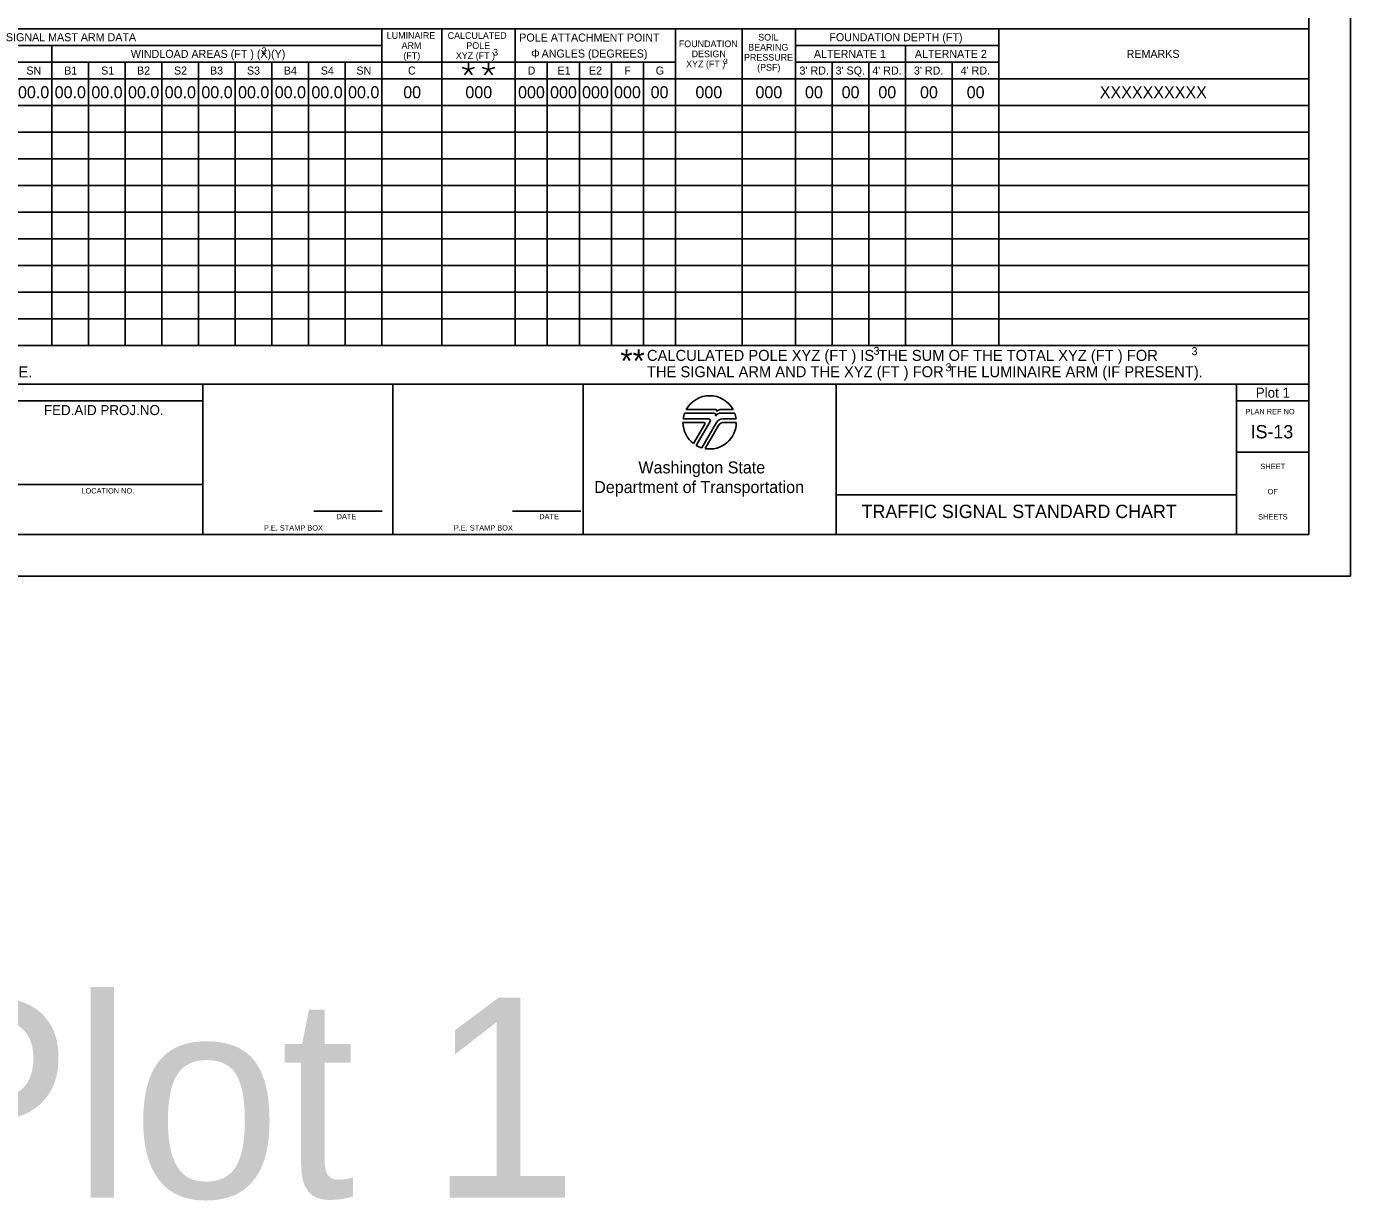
# Model space of a CAD drawing. Extents: x 99999.1 to 100045.6, y 99995 to 100042.
# Drawn here: x 100006.13 to 100016.06, y 99995.01 to 100003.81 of the extents above; entities that cross this region are included whole.
import ezdxf

# ---------------------------------------------------------------- set-up
doc = ezdxf.new("R2010")
doc.units = 0
for name, color, linetype in [('Level 20', 7, 'Continuous'), ('Level 40', 7, 'Continuous'), ('Level 51', 7, 'Continuous'), ('Level 55', 7, 'Continuous'), ('SH_GI_PlotLimits', 7, 'Continuous'), ('SH_GI_SheetBorder', 7, 'Continuous'), ('SH_GI_SheetLocationText', 7, 'Continuous'), ('SH_GI_SheetTextInCells', 7, 'Continuous'), ('SH_GI_TitleBlockText', 7, 'Continuous'), ('SH_GI_WSDOTLogo', 7, 'Continuous'), ('TR_SG_SignalsUserLevel1New', 7, 'Continuous')]:
    doc.layers.add(name, color=color, linetype=linetype)

msp = doc.modelspace()

# ---------------------------------------------------------------- linework, layer by layer
at = {"layer": 'Level 20'}
for p, q in [((100009.401, 100003.4998), (100009.448, 100003.4845)), ((100009.448, 100003.4845), (100009.419, 100003.4445)), ((100009.448, 100003.4845), (100009.448, 100003.534)), ((100009.448, 100003.4845), (100009.495, 100003.4998)), ((100009.448, 100003.4845), (100009.4771, 100003.4445)), ((100009.5518, 100003.4998), (100009.5988, 100003.4845)), ((100009.5988, 100003.4845), (100009.5697, 100003.4445)), ((100009.5988, 100003.4845), (100009.5988, 100003.534)), ((100009.5988, 100003.4845), (100009.6458, 100003.4998)), ((100009.5988, 100003.4845), (100009.6278, 100003.4445))]:
    msp.add_line(p, q, dxfattribs=at)
at = {"layer": 'Level 40'}
for p, q in [((100000, 100003.7903), (100015.7438, 100003.7903)), ((100008.8, 100003.7903), (100008.8, 100001.4153)), ((100009.25, 100003.7903), (100009.25, 100001.4153)), ((100009.8, 100003.7903), (100009.8, 100001.4153)), ((100011, 100003.7903), (100011, 100001.4153)), ((100011.5, 100003.7903), (100011.5, 100001.4153)), ((100011.9, 100003.7903), (100011.9, 100001.4153)), ((100013.425, 100003.7903), (100013.425, 100001.4153)), ((100003.85, 100003.6653), (100008.8, 100003.6653)), ((100006.325, 100003.6653), (100006.325, 100001.4153)), ((100011.9, 100003.6653), (100013.425, 100003.6653)), ((100012.725, 100003.6653), (100012.725, 100001.4153)), ((100003.35, 100003.5403), (100011, 100003.5403)), ((100006.6, 100003.5403), (100006.6, 100001.4153)), ((100006.875, 100003.5403), (100006.875, 100001.4153)), ((100007.15, 100003.5403), (100007.15, 100001.4153)), ((100007.425, 100003.5403), (100007.425, 100001.4153)), ((100007.7, 100003.5403), (100007.7, 100001.4153)), ((100007.975, 100003.5403), (100007.975, 100001.4153)), ((100008.25, 100003.5403), (100008.25, 100001.4153)), ((100008.525, 100003.5403), (100008.525, 100001.4153)), ((100010.04, 100003.5403), (100010.04, 100001.4153)), ((100010.28, 100003.5403), (100010.28, 100001.4153)), ((100010.52, 100003.5403), (100010.52, 100001.4153)), ((100010.76, 100003.5403), (100010.76, 100001.4153)), ((100011.9, 100003.5403), (100013.425, 100003.5403)), ((100012.175, 100003.5403), (100012.175, 100001.4153)), ((100012.45, 100003.5403), (100012.45, 100001.4153)), ((100013.075, 100003.5403), (100013.075, 100001.4153)), ((100000, 100003.4153), (100015.75, 100003.4153)), ((100000, 100003.2153), (100015.75, 100003.2153)), ((100000, 100003.0153), (100015.75, 100003.0153)), ((100000, 100002.8153), (100015.75, 100002.8153)), ((100000, 100002.6153), (100015.75, 100002.6153)), ((100000, 100002.4153), (100015.75, 100002.4153)), ((100000, 100002.2153), (100015.75, 100002.2153)), ((100000, 100002.0153), (100015.75, 100002.0153)), ((100000, 100001.8153), (100015.75, 100001.8153)), ((100000, 100001.6153), (100015.75, 100001.6153)), ((100000, 100001.4153), (100015.7438, 100001.4153))]:
    msp.add_line(p, q, dxfattribs=at)
at = {"layer": 'SH_GI_PlotLimits'}
msp.add_lwpolyline([(99999.0625, 99999.6875), (100016.0625, 99999.6875), (100016.0625, 100010.6875), (99999.0625, 100010.6875)], close=True, dxfattribs=at)
at = {"layer": 'SH_GI_SheetBorder'}
for p, q in [((100015.75, 100010.375), (100015.75, 100000)), ((100000, 100001.1259), (100015.75, 100001.1259)), ((100007.4566, 100000), (100007.4566, 100001.1259)), ((100008.8828, 100000), (100008.8828, 100001.1259)), ((100010.3089, 100001.1259), (100010.3089, 100000)), ((100012.2055, 100001.1259), (100012.2055, 100000)), ((100015.2079, 100001.1259), (100015.2079, 100000)), ((100000, 100001.0008), (100007.4566, 100001.0008)), ((100015.2079, 100001.0008), (100015.75, 100001.0008)), ((100015.2079, 100000.6176), (100015.75, 100000.6176)), ((100007.4566, 100000.3753), (100005.4466, 100000.3753)), ((100012.2055, 100000.2955), (100015.2079, 100000.2955)), ((100008.2903, 100000.1733), (100008.802, 100000.1733)), ((100009.7797, 100000.1733), (100010.2914, 100000.1733)), ((100000, 100000), (100015.75, 100000))]:
    msp.add_line(p, q, dxfattribs=at)
at = {"layer": 'SH_GI_WSDOTLogo'}
for p, q in [((100011.2894, 100000.9094), (100011.0697, 100000.9094)), ((100011.303, 100000.9354), (100011.0815, 100000.9354)), ((100011.433, 100000.9354), (100011.3351, 100000.9354)), ((100011.343, 100000.9094), (100011.3429, 100000.9094)), ((100011.4448, 100000.9094), (100011.343, 100000.9094)), ((100011.0572, 100000.84), (100011.2148, 100000.84)), ((100011.059, 100000.8661), (100011.2496, 100000.8661)), ((100011.222, 100000.8277), (100011.1364, 100000.6807)), ((100011.261, 100000.8464), (100011.1567, 100000.6672)), ((100011.1989, 100000.6487), (100011.3089, 100000.839)), ((100011.2244, 100000.6428), (100011.3242, 100000.8156)), ((100011.3558, 100000.8661), (100011.4555, 100000.8661)), ((100011.3655, 100000.8394), (100011.4572, 100000.8394))]:
    msp.add_line(p, q, dxfattribs=at)
for centre, radius, start, end in [((100011.2572, 100000.84), 0.2, 28.47865, 151.53204), ((100011.2572, 100000.84), 0.2, 159.69598, 172.50569), ((100011.2894, 100000.8946), 0.0148, 327.8418, 89.99855), ((100011.3429, 100000.861), 0.0484, 89.99529, 147.82376), ((100011.303, 100000.9263), 0.00903, 329.87418, 90.00328), ((100011.3352, 100000.9066), 0.0287, 90.00721, 148.16763), ((100011.2572, 100000.84), 0.2, 7.49431, 20.29406), ((100011.2572, 100000.84), 0.2, 179.99864, 232.84327), ((100011.2149, 100000.8318), 0.0082, 329.74356, 90), ((100011.2572, 100000.84), 0.2, 260.54554, 359.80857), ((100011.2497, 100000.853), 0.0131, 329.76834, 90), ((100011.3558, 100000.8119), 0.0542, 90, 149.99738), ((100011.3654, 100000.7918), 0.0476, 90, 150.05432), ((100011.2572, 100000.84), 0.2, 239.79292, 253.0448)]:
    msp.add_arc(centre, radius, start, end, dxfattribs=at)

# ---------------------------------------------------------------- texts
at = {"layer": 'Level 40'}
msp.add_text('2', height=0.05, dxfattribs=at).set_placement((100007.8967, 100003.602))
at = {"layer": 'Level 51'}
for s, height, p in [('SIGNAL MAST ARM DATA', 0.06, (100005.9802, 100003.6978)), ('LUMINAIRE', 0.05, (100008.8359, 100003.7157)), ('CALCULATED', 0.05, (100009.2928, 100003.7155)), ('POLE ATTACHMENT POINT', 0.06, (100009.8296, 100003.6953)), ('FOUNDATION DEPTH (FT)', 0.06, (100012.1549, 100003.6978)), ('ARM', 0.05, (100008.9472, 100003.6403)), ('POLE', 0.05, (100009.4328, 100003.6401)), ('FOUNDATION', 0.05, (100011.026, 100003.6532)), ('BEARING', 0.05, (100011.5463, 100003.6274)), ('SOIL', 0.05, (100011.6212, 100003.7028)), ('WINDLOAD AREAS (FT ) (X)(Y)', 0.06, (100006.9169, 100003.5728)), ('(FT)', 0.05, (100008.9609, 100003.5649)), ('XYZ (FT )', 0.05, (100009.3541, 100003.5647)), ('3', 0.05, (100009.6332, 100003.5903)), ('Φ', 0.06, (100009.9186, 100003.5753)), (' ANGLES (DEGREES)', 0.06, (100009.9748, 100003.5753)), ('DESIGN', 0.05, (100011.1222, 100003.5778)), ('3', 0.04, (100011.3621, 100003.5272)), ('PRESSURE', 0.05, (100011.5146, 100003.552)), ('ALTERNATE 1', 0.06, (100012.0386, 100003.5728)), ('ALTERNATE 2', 0.06, (100012.796, 100003.5728)), ('REMARKS', 0.06, (100014.3838, 100003.5728)), ('SN', 0.06, (100006.1337, 100003.4478)), ('B1', 0.06, (100006.4172, 100003.4478)), ('S1', 0.06, (100006.6945, 100003.4478)), ('B2', 0.06, (100006.9633, 100003.4478)), ('S2', 0.06, (100007.2405, 100003.4478)), ('B3', 0.06, (100007.5104, 100003.4478)), ('S3', 0.06, (100007.7876, 100003.4478)), ('B4', 0.06, (100008.0638, 100003.4478)), ('S4', 0.06, (100008.3411, 100003.4478)), ('SN', 0.06, (100008.6087, 100003.4478)), ('C', 0.06, (100008.995, 100003.4481)), ('D', 0.06, (100009.8923, 100003.4478)), ('E1', 0.06, (100010.117, 100003.4478)), ('E2', 0.06, (100010.3519, 100003.4478)), ('F', 0.06, (100010.6174, 100003.4478)), ('G', 0.06, (100010.8523, 100003.4478)), ('XYZ (FT )', 0.05, (100011.0807, 100003.5024)), ('(PSF)', 0.05, (100011.6132, 100003.4766)), ("3' RD.", 0.06, (100011.9307, 100003.4478)), ("3' SQ.", 0.06, (100012.2015, 100003.4478)), ("4' RD.", 0.06, (100012.4765, 100003.4478)), ("3' RD.", 0.06, (100012.789, 100003.4478)), ("4' RD.", 0.06, (100013.139, 100003.4478))]:
    msp.add_text(s, height=height, dxfattribs=at).set_placement(p)
at = {"layer": 'Level 55'}
for s, p in [('00.0', (100006.0711, 100003.2703)), ('00.0', (100006.3461, 100003.2703)), ('00.0', (100006.6211, 100003.2703)), ('00.0', (100006.8961, 100003.2703)), ('00.0', (100007.1711, 100003.2703)), ('00.0', (100007.4461, 100003.2703)), ('00.0', (100007.7211, 100003.2703)), ('00.0', (100007.9961, 100003.2703)), ('00.0', (100008.2711, 100003.2703)), ('00.0', (100008.5461, 100003.2703)), ('00', (100008.9596, 100003.2703)), ('000', (100009.4256, 100003.2703)), ('000', (100009.8206, 100003.2703)), ('000', (100010.0606, 100003.2703)), ('000', (100010.3006, 100003.2703)), ('000', (100010.5406, 100003.2703)), ('00', (100010.8146, 100003.2703)), ('000', (100011.1506, 100003.2703)), ('000', (100011.6006, 100003.2703)), ('00', (100011.9721, 100003.2703)), ('00', (100012.2471, 100003.2703)), ('00', (100012.5221, 100003.2703)), ('00', (100012.8346, 100003.2703)), ('00', (100013.1846, 100003.2703)), ('XXXXXXXXXX', (100014.1824, 100003.2703))]:
    msp.add_text(s, height=0.09, dxfattribs=at).set_placement(p)
at = {"layer": 'SH_GI_SheetBorder'}
msp.add_text('PLAN REF NO', height=0.040032, dxfattribs=at).set_placement((100015.2747, 100000.9008))
at = {"layer": 'SH_GI_SheetLocationText'}
for height, p in [(0.075, (100015.3518, 100001.025)), (1.5, (100005.1422, 99995.0267))]:
    msp.add_text('Plot 1', height=height, dxfattribs=at).set_placement(p)
at = {"layer": 'SH_GI_SheetTextInCells'}
for s, height, p in [('FED.AID PROJ.NO.', 0.07506, (100006.2652, 100000.8945)), ('Washington State', 0.090072, (100010.7229, 100000.4571)), ('SHEET', 0.04003, (100015.3877, 100000.4896)), ('Department of Transportation', 0.090072, (100010.3916, 100000.3101)), ('LOCATION NO.', 0.040032, (100006.5465, 100000.3067)), ('OF', 0.04003, (100015.4406, 100000.3008)), ('DATE', 0.04003, (100008.4597, 100000.1141)), ('DATE', 0.04003, (100009.9794, 100000.1141)), ('SHEETS', 0.04003, (100015.3698, 100000.112)), ('P.E. STAMP BOX', 0.040032, (100007.915, 100000.0286)), ('P.E. STAMP BOX', 0.040032, (100009.339, 100000.0286))]:
    msp.add_text(s, height=height, dxfattribs=at).set_placement(p)
at = {"layer": 'SH_GI_TitleBlockText'}
for s, p in [('IS-13', (100015.3134, 100000.72)), ('TRAFFIC SIGNAL STANDARD CHART', (100012.3969, 100000.1224))]:
    msp.add_text(s, height=0.1, dxfattribs=at).set_placement(p)
at = {"layer": 'TR_SG_SignalsUserLevel1New'}
for s, height, p in [('**', 0.175, (100010.5882, 100001.2132)), ('CALCULATED POLE XYZ (FT ) IS THE SUM OF THE TOTAL XYZ (FT ) FOR', 0.0825, (100010.7871, 100001.3009)), ('3', 0.06, (100012.4859, 100001.3464)), ('3', 0.06, (100014.8707, 100001.3439)), ('3', 0.06, (100014.8707, 100001.3439)), ('3', 0.06, (100013.0258, 100001.2225)), ('IF NO ELEVATION SHOWN, ELEVATION SHALL MATCH TOP OF SIDEWALK OR ROAD SHOULDER AS APPLICABLE.', 0.0825, (100000.153, 100001.177)), ('THE SIGNAL ARM AND THE XYZ (FT ) FOR THE LUMINAIRE ARM (IF PRESENT).', 0.0825, (100010.7871, 100001.1784))]:
    msp.add_text(s, height=height, dxfattribs=at).set_placement(p)

doc.saveas('drawing.dxf')
